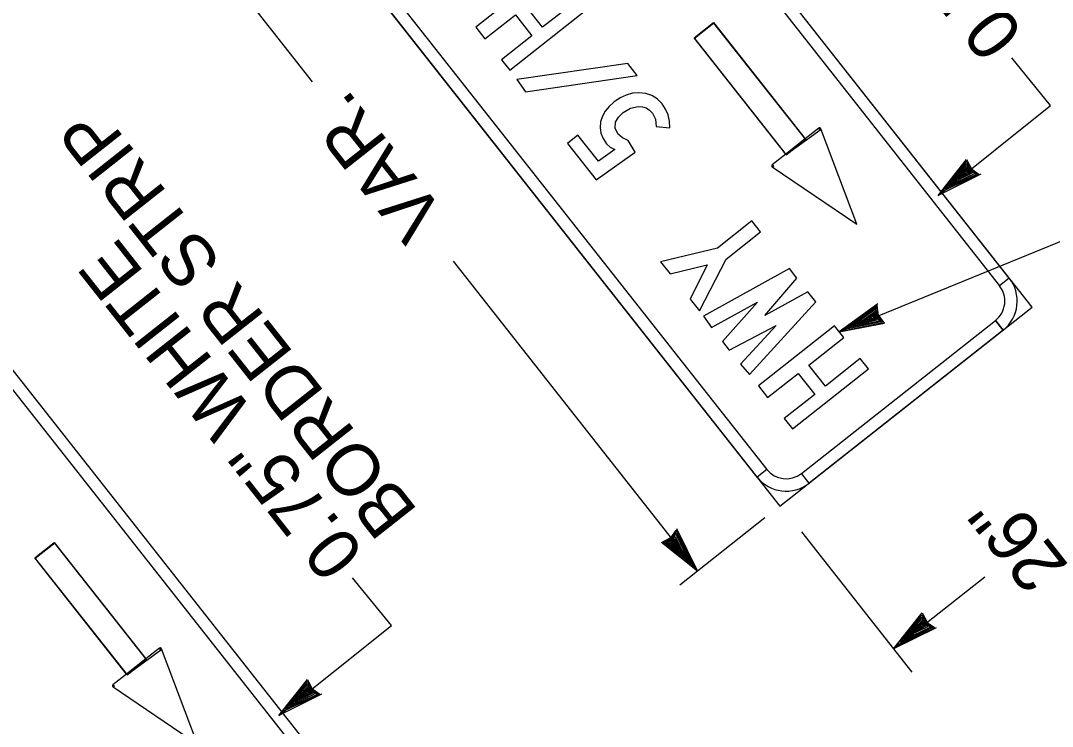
# Model space of a CAD drawing. Extents: x 671946 to 673995, y 1673066 to 1674936.
# Drawn here: x 672680.8 to 672764.3, y 1673606 to 1673663.1 of the extents above; entities that cross this region are included whole.
import ezdxf

# ---------------------------------------------------------------- set-up
doc = ezdxf.new("R2010")
doc.units = 0
doc.layers.add('C-ANNO-SYMB', color=7, linetype='Continuous')
doc.layers.add('Level 1', color=7, linetype='Continuous')

msp = doc.modelspace()

# ---------------------------------------------------------------- linework, layer by layer
at = {"layer": 'C-ANNO-SYMB'}
for p, q in [((672762.708, 1673639.935), (672710.703, 1673705.901)), ((672760.851, 1673642.291), (672712.561, 1673703.545)), ((672711.775, 1673702.926), (672760.065, 1673641.672)), ((672690.285, 1673689.804), (672742.29, 1673623.838)), ((672740.433, 1673626.194), (672692.143, 1673687.449)), ((672692.928, 1673688.068), (672741.218, 1673626.813)), ((672709.345, 1673597.867), (672657.341, 1673663.833)), ((672735.333, 1673661.737), (672736.904, 1673662.975)), ((672736.947, 1673662.921), (672735.376, 1673661.683)), ((672736.904, 1673662.975), (672736.904, 1673662.975)), ((672736.904, 1673662.975), (672736.904, 1673662.975)), ((672736.904, 1673662.975), (672744.333, 1673653.552)), ((672744.376, 1673653.497), (672736.947, 1673662.921)), ((672707.488, 1673600.222), (672659.198, 1673661.477)), ((672742.762, 1673652.314), (672735.333, 1673661.737)), ((672735.376, 1673661.683), (672735.376, 1673661.683)), ((672735.376, 1673661.683), (672735.376, 1673661.683)), ((672735.376, 1673661.683), (672742.805, 1673652.259)), ((672658.413, 1673660.858), (672706.703, 1673599.603)), ((672745.63, 1673654.322), (672742.805, 1673652.259)), ((672745.432, 1673654.418), (672744.333, 1673653.552)), ((672745.494, 1673654.34), (672745.432, 1673654.418)), ((672745.432, 1673654.418), (672745.494, 1673654.34)), ((672745.475, 1673654.364), (672745.537, 1673654.285)), ((672745.537, 1673654.285), (672745.475, 1673654.364)), ((672745.587, 1673654.376), (672745.494, 1673654.34)), ((672745.494, 1673654.34), (672745.587, 1673654.376)), ((672745.537, 1673654.285), (672745.63, 1673654.322)), ((672745.537, 1673654.285), (672745.63, 1673654.322)), ((672748.5, 1673646.65), (672745.587, 1673654.376)), ((672742.762, 1673652.314), (672744.333, 1673653.552)), ((672742.762, 1673652.314), (672744.333, 1673653.552)), ((672744.333, 1673653.552), (672742.762, 1673652.314)), ((672744.376, 1673653.497), (672742.805, 1673652.259)), ((672742.805, 1673652.259), (672744.376, 1673653.497)), ((672742.762, 1673652.314), (672741.663, 1673651.447)), ((672741.663, 1673651.447), (672741.725, 1673651.368)), ((672741.725, 1673651.368), (672741.663, 1673651.447)), ((672741.725, 1673651.368), (672741.668, 1673651.286)), ((672741.668, 1673651.286), (672741.725, 1673651.368)), ((672741.668, 1673651.286), (672748.5, 1673646.65)), ((672741.768, 1673651.314), (672741.706, 1673651.392)), ((672741.706, 1673651.392), (672741.768, 1673651.314)), ((672741.711, 1673651.232), (672741.768, 1673651.314)), ((672741.768, 1673651.314), (672741.711, 1673651.232)), ((672748.5, 1673646.65), (672748.5, 1673646.65)), ((672748.5, 1673646.65), (672748.5, 1673646.65)), ((672748.543, 1673646.596), (672748.543, 1673646.596)), ((672748.543, 1673646.596), (672748.543, 1673646.596)), ((672760.851, 1673642.291), (672760.065, 1673641.672)), ((672760.851, 1673642.291), (672760.065, 1673641.672)), ((672760.065, 1673641.672), (672760.065, 1673641.672)), ((672760.065, 1673641.672), (672760.065, 1673641.672)), ((672742.29, 1673623.838), (672762.708, 1673639.935)), ((672762.708, 1673639.935), (672762.708, 1673639.935)), ((672762.708, 1673639.935), (672762.708, 1673639.935)), ((672744.027, 1673626.481), (672759.733, 1673638.863)), ((672759.733, 1673638.863), (672760.352, 1673638.078)), ((672760.352, 1673638.078), (672759.733, 1673638.863)), ((672760.352, 1673638.078), (672744.646, 1673625.696)), ((672741.218, 1673626.813), (672740.433, 1673626.194)), ((672741.218, 1673626.813), (672740.433, 1673626.194)), ((672744.646, 1673625.696), (672744.027, 1673626.481)), ((672744.027, 1673626.481), (672744.027, 1673626.481)), ((672744.027, 1673626.481), (672744.027, 1673626.481)), ((672744.646, 1673625.696), (672744.027, 1673626.481)), ((672681.971, 1673619.669), (672683.541, 1673620.907)), ((672683.584, 1673620.853), (672682.014, 1673619.614)), ((672683.541, 1673620.907), (672683.541, 1673620.907)), ((672683.541, 1673620.907), (672683.541, 1673620.907)), ((672683.541, 1673620.907), (672690.97, 1673611.483)), ((672691.013, 1673611.429), (672683.584, 1673620.853)), ((672689.4, 1673610.245), (672681.971, 1673619.669)), ((672682.014, 1673619.614), (672682.014, 1673619.614)), ((672682.014, 1673619.614), (672682.014, 1673619.614)), ((672682.014, 1673619.614), (672689.443, 1673610.191)), ((672692.268, 1673612.253), (672689.443, 1673610.191)), ((672692.07, 1673612.35), (672690.97, 1673611.483)), ((672692.132, 1673612.271), (672692.07, 1673612.35)), ((672692.07, 1673612.35), (672692.132, 1673612.271)), ((672692.113, 1673612.296), (672692.175, 1673612.217)), ((672692.175, 1673612.217), (672692.113, 1673612.296)), ((672692.225, 1673612.308), (672692.132, 1673612.271)), ((672692.132, 1673612.271), (672692.225, 1673612.308)), ((672692.175, 1673612.217), (672692.268, 1673612.253)), ((672692.175, 1673612.217), (672692.268, 1673612.253)), ((672695.138, 1673604.582), (672692.225, 1673612.308)), ((672689.4, 1673610.245), (672690.97, 1673611.483)), ((672689.4, 1673610.245), (672690.97, 1673611.483)), ((672690.97, 1673611.483), (672689.4, 1673610.245)), ((672691.013, 1673611.429), (672689.443, 1673610.191)), ((672689.443, 1673610.191), (672691.013, 1673611.429)), ((672689.4, 1673610.245), (672688.3, 1673609.378)), ((672688.3, 1673609.378), (672688.362, 1673609.3)), ((672688.362, 1673609.3), (672688.3, 1673609.378)), ((672688.362, 1673609.3), (672688.305, 1673609.218)), ((672688.305, 1673609.218), (672688.362, 1673609.3)), ((672688.305, 1673609.218), (672695.138, 1673604.582)), ((672688.405, 1673609.245), (672688.343, 1673609.324)), ((672688.343, 1673609.324), (672688.405, 1673609.245)), ((672688.348, 1673609.163), (672688.405, 1673609.245)), ((672688.405, 1673609.245), (672688.348, 1673609.163))]:
    msp.add_line(p, q, dxfattribs=at)
for points in [[(672726.575, 1673663.963), (672725.908, 1673664.808), (672723.081, 1673662.579), (672721.747, 1673664.271), (672724.575, 1673666.5), (672723.832, 1673667.442), (672717.671, 1673662.585), (672718.413, 1673661.643), (672720.884, 1673663.591), (672722.218, 1673661.899), (672719.747, 1673659.951), (672720.413, 1673659.106)], [(672730.735, 1673658.686), (672729.98, 1673659.643), (672720.997, 1673658.365), (672721.701, 1673657.368)], [(672733.379, 1673654.455), (672733.346, 1673654.994), (672733.228, 1673655.494), (672733.028, 1673655.956), (672732.746, 1673656.383), (672732.36, 1673656.782), (672731.921, 1673657.067), (672731.427, 1673657.234), (672730.875, 1673657.286), (672730.351, 1673657.237), (672729.839, 1673657.093), (672729.342, 1673656.858), (672728.855, 1673656.528), (672728.457, 1673656.169), (672728.142, 1673655.782), (672727.916, 1673655.375), (672727.775, 1673654.943), (672727.733, 1673654.476), (672727.795, 1673654.022), (672727.968, 1673653.576), (672728.246, 1673653.147), (672728.533, 1673652.884), (672728.932, 1673652.681), (672727.595, 1673651.736), (672725.938, 1673653.838), (672725.092, 1673653.171), (672727.405, 1673650.237), (672730.567, 1673652.488), (672730.005, 1673653.427), (672729.533, 1673653.635), (672729.163, 1673653.971), (672728.949, 1673654.421), (672728.985, 1673654.899), (672729.209, 1673655.308), (672729.587, 1673655.686), (672730.192, 1673656.043), (672730.813, 1673656.177), (672731.152, 1673656.154), (672731.455, 1673656.053), (672731.732, 1673655.877), (672731.974, 1673655.624), (672732.22, 1673655.137), (672732.272, 1673654.539)], [(672733.39, 1673642.645), (672736.39, 1673643.348), (672735.023, 1673640.574), (672735.767, 1673639.63), (672737.927, 1673643.822), (672740.718, 1673646.022), (672740.018, 1673646.911), (672737.226, 1673644.71), (672732.632, 1673643.608)], [(672745.182, 1673640.361), (672744.533, 1673641.183), (672741.063, 1673639.269), (672743.658, 1673642.294), (672743.058, 1673643.055), (672736.106, 1673639.2), (672736.74, 1673638.292), (672740.483, 1673640.354), (672737.642, 1673637.148), (672738.19, 1673636.453), (672741.986, 1673638.448), (672739.087, 1673635.315), (672739.828, 1673634.479)], [(672749.457, 1673634.938), (672748.79, 1673635.783), (672745.963, 1673633.554), (672744.629, 1673635.246), (672747.457, 1673637.475), (672746.714, 1673638.417), (672740.553, 1673633.56), (672741.295, 1673632.618), (672743.766, 1673634.566), (672745.1, 1673632.874), (672742.629, 1673630.926), (672743.295, 1673630.081)]]:
    msp.add_lwpolyline(points, close=True, dxfattribs=at)
for centre, radius, start, end in [((672745.494, 1673654.34), 0.1, 21.14769, 128.25069), ((672741.725, 1673651.368), 0.1, 128.25069, 235.35312), ((672758.495, 1673640.434), 3, 308.25039, 38.2506), ((672758.495, 1673640.434), 2, 308.25039, 38.2506), ((672742.789, 1673628.052), 2, 218.25075, 308.25039), ((672742.789, 1673628.052), 3, 218.25075, 308.25039), ((672692.132, 1673612.271), 0.1, 21.14769, 128.25069), ((672688.362, 1673609.3), 0.1, 128.25069, 235.35312)]:
    msp.add_arc(centre, radius, start, end, dxfattribs=at)
at = {"layer": 'Level 1'}
for p, q in [((672704.456, 1673658.174), (672683.642, 1673684.577)), ((672755.083, 1673648.981), (672757.402, 1673651.891)), ((672755.3, 1673649.217), (672757.384, 1673651.742)), ((672755.652, 1673649.493), (672757.382, 1673651.574)), ((672757.382, 1673651.574), (672757.52, 1673651.314)), ((672757.384, 1673651.742), (672757.725, 1673651.177)), ((672757.402, 1673651.891), (672757.795, 1673651.132)), ((672758.543, 1673650.687), (672755.083, 1673648.981)), ((672758.185, 1673650.672), (672755.342, 1673649.249)), ((672758.351, 1673650.634), (672755.503, 1673649.341)), ((672755.87, 1673649.593), (672757.425, 1673651.309)), ((672758.064, 1673650.744), (672755.87, 1673649.593)), ((672755.942, 1673649.716), (672757.383, 1673651.443)), ((672758.064, 1673650.744), (672755.942, 1673649.716)), ((672756.376, 1673650.056), (672757.369, 1673651.165)), ((672757.885, 1673650.803), (672756.376, 1673650.056)), ((672756.763, 1673650.325), (672757.334, 1673651.037)), ((672757.723, 1673650.842), (672756.763, 1673650.325)), ((672757.428, 1673651.177), (672756.922, 1673650.419)), ((672757.098, 1673650.621), (672757.364, 1673650.96)), ((672757.615, 1673650.892), (672757.098, 1673650.621)), ((672757.334, 1673651.037), (672757.615, 1673650.892)), ((672757.364, 1673650.96), (672757.446, 1673650.895)), ((672757.369, 1673651.165), (672757.723, 1673650.842)), ((672757.383, 1673651.443), (672758.064, 1673650.744)), ((672757.425, 1673651.309), (672757.885, 1673650.803)), ((672757.804, 1673650.906), (672757.428, 1673651.177)), ((672757.446, 1673650.895), (672757.804, 1673650.906)), ((672757.52, 1673651.314), (672758.064, 1673650.744)), ((672757.725, 1673651.177), (672758.396, 1673650.705)), ((672757.795, 1673651.132), (672758.037, 1673650.822)), ((672758.037, 1673650.822), (672758.351, 1673650.634)), ((672758.396, 1673650.705), (672758.177, 1673650.768)), ((672758.177, 1673650.768), (672758.185, 1673650.672)), ((672756.922, 1673650.419), (672756.669, 1673650.318)), ((672735.617, 1673618.578), (672715.856, 1673643.645)), ((672750.205, 1673640.216), (672747.085, 1673637.946)), ((672750.026, 1673639.905), (672747.443, 1673638.051)), ((672750.069, 1673640.07), (672747.599, 1673638.151)), ((672750.034, 1673639.765), (672747.993, 1673638.359)), ((672750.034, 1673639.765), (672748.136, 1673638.364)), ((672750.107, 1673639.854), (672750.026, 1673639.905)), ((672750.284, 1673639.018), (672750.034, 1673639.765)), ((672750.335, 1673638.837), (672750.034, 1673639.765)), ((672750.089, 1673639.704), (672750.069, 1673640.07)), ((672750.153, 1673640.077), (672750.107, 1673639.854)), ((672750.259, 1673639.263), (672750.153, 1673640.077)), ((672747.993, 1673638.359), (672750.235, 1673638.936)), ((672750.002, 1673639.579), (672748.638, 1673638.59)), ((672748.638, 1673638.59), (672750.082, 1673638.954)), ((672749.961, 1673639.417), (672749.057, 1673638.808)), ((672749.057, 1673638.808), (672749.953, 1673638.982)), ((672750.12, 1673639), (672749.214, 1673638.905)), ((672749.955, 1673639.299), (672749.475, 1673638.967)), ((672749.475, 1673638.967), (672749.899, 1673639.044)), ((672749.88, 1673639.147), (672750.056, 1673639.459)), ((672749.899, 1673639.044), (672749.88, 1673639.147)), ((672749.953, 1673638.982), (672749.955, 1673639.299)), ((672750.082, 1673638.954), (672749.961, 1673639.417)), ((672750.235, 1673638.936), (672750.002, 1673639.579)), ((672750.056, 1673639.459), (672750.12, 1673639)), ((672750.251, 1673639.346), (672750.089, 1673639.704)), ((672750.741, 1673638.645), (672750.251, 1673639.346)), ((672750.601, 1673638.698), (672750.259, 1673639.263)), ((672750.45, 1673638.774), (672750.284, 1673639.018)), ((672747.085, 1673637.946), (672750.741, 1673638.645)), ((672747.396, 1673638.029), (672750.601, 1673638.698)), ((672747.599, 1673638.151), (672747.396, 1673638.029)), ((672747.443, 1673638.051), (672747.566, 1673638.221)), ((672747.566, 1673638.221), (672748.314, 1673638.731)), ((672747.803, 1673638.211), (672750.45, 1673638.774)), ((672748.314, 1673638.731), (672747.803, 1673638.211)), ((672748.136, 1673638.364), (672750.335, 1673638.837)), ((672748.531, 1673638.57), (672748.918, 1673638.859)), ((672749.007, 1673638.728), (672748.531, 1673638.57)), ((672749.214, 1673638.905), (672749.007, 1673638.728)), ((672741.077, 1673622.883), (672734.173, 1673617.44)), ((672733.157, 1673620.88), (672733.856, 1673621.561)), ((672733.286, 1673621.016), (672733.856, 1673621.561)), ((672733.291, 1673620.921), (672733.797, 1673621.382)), ((672733.423, 1673621.222), (672733.896, 1673621.893)), ((672733.468, 1673621.292), (672733.778, 1673621.533)), ((672733.778, 1673621.533), (672733.966, 1673621.848)), ((672733.797, 1673621.382), (672734.543, 1673619.872)), ((672733.896, 1673621.893), (672733.832, 1673621.674)), ((672733.832, 1673621.674), (672733.928, 1673621.682)), ((672733.856, 1673621.561), (672734.883, 1673619.438)), ((672733.856, 1673621.561), (672735.006, 1673619.366)), ((672733.914, 1673622.04), (672735.617, 1673618.578)), ((672733.928, 1673621.682), (672735.35, 1673618.838)), ((672733.966, 1673621.848), (672735.258, 1673618.999)), ((672744.021, 1673621.757), (672752.976, 1673610.397)), ((672732.709, 1673620.9), (672733.468, 1673621.292)), ((672735.617, 1673618.578), (672732.709, 1673620.9)), ((672732.857, 1673620.881), (672733.423, 1673621.222)), ((672735.382, 1673618.796), (672732.857, 1673620.881)), ((672733.026, 1673620.878), (672733.286, 1673621.016)), ((672735.106, 1673619.147), (672733.026, 1673620.878)), ((672734.883, 1673619.438), (672733.157, 1673620.88)), ((672735.006, 1673619.366), (672733.291, 1673620.921)), ((672733.694, 1673621.3), (672733.423, 1673620.924)), ((672733.423, 1673620.924), (672734.181, 1673620.418)), ((672733.435, 1673620.866), (672733.757, 1673621.219)), ((672734.543, 1673619.872), (672733.435, 1673620.866)), ((672733.562, 1673620.831), (672733.708, 1673621.112)), ((672734.274, 1673620.259), (672733.562, 1673620.831)), ((672733.639, 1673620.861), (672733.704, 1673620.943)), ((672733.979, 1673620.595), (672733.639, 1673620.861)), ((672733.704, 1673620.943), (672733.694, 1673621.3)), ((672733.708, 1673621.112), (672733.979, 1673620.595)), ((672733.757, 1673621.219), (672734.274, 1673620.259)), ((672734.181, 1673620.418), (672734.281, 1673620.165)), ((672734.281, 1673620.165), (672734.629, 1673619.804)), ((672734.629, 1673619.804), (672734.421, 1673620.239)), ((672735.32, 1673619.045), (672734.896, 1673619.845)), ((672734.896, 1673619.845), (672735.106, 1673619.147)), ((672735.258, 1673618.999), (672735.382, 1673618.796)), ((672735.35, 1673618.838), (672735.32, 1673619.045)), ((672751.482, 1673612.292), (672758.87, 1673618.117)), ((672751.482, 1673612.292), (672753.803, 1673615.201)), ((672751.7, 1673612.528), (672753.785, 1673615.052)), ((672752.051, 1673612.804), (672753.782, 1673614.884)), ((672752.341, 1673613.027), (672753.784, 1673614.753)), ((672753.782, 1673614.884), (672753.92, 1673614.624)), ((672753.784, 1673614.753), (672754.464, 1673614.054)), ((672753.785, 1673615.052), (672754.126, 1673614.487)), ((672753.803, 1673615.201), (672754.195, 1673614.441)), ((672754.943, 1673613.996), (672751.482, 1673612.292)), ((672754.586, 1673613.982), (672751.742, 1673612.56)), ((672754.751, 1673613.944), (672751.903, 1673612.652)), ((672752.27, 1673612.904), (672753.825, 1673614.619)), ((672754.464, 1673614.054), (672752.27, 1673612.904)), ((672754.464, 1673614.054), (672752.341, 1673613.027)), ((672752.775, 1673613.367), (672753.77, 1673614.475)), ((672754.285, 1673614.113), (672752.775, 1673613.367)), ((672753.163, 1673613.635), (672753.734, 1673614.347)), ((672754.123, 1673614.152), (672753.163, 1673613.635)), ((672753.828, 1673614.487), (672753.322, 1673613.729)), ((672753.498, 1673613.931), (672753.764, 1673614.271)), ((672754.016, 1673614.202), (672753.498, 1673613.931)), ((672753.734, 1673614.347), (672754.016, 1673614.202)), ((672753.764, 1673614.271), (672753.846, 1673614.205)), ((672753.77, 1673614.475), (672754.123, 1673614.152)), ((672753.825, 1673614.619), (672754.285, 1673614.113)), ((672754.204, 1673614.216), (672753.828, 1673614.487)), ((672753.846, 1673614.205), (672754.204, 1673614.216)), ((672753.92, 1673614.624), (672754.464, 1673614.054)), ((672754.126, 1673614.487), (672754.796, 1673614.014)), ((672754.195, 1673614.441), (672754.437, 1673614.132)), ((672754.437, 1673614.132), (672754.751, 1673613.944)), ((672754.796, 1673614.014), (672754.577, 1673614.077)), ((672754.577, 1673614.077), (672754.586, 1673613.982)), ((672753.069, 1673613.629), (672752.707, 1673613.281)), ((672752.707, 1673613.281), (672753.143, 1673613.489)), ((672753.322, 1673613.729), (672753.069, 1673613.629)), ((672751.903, 1673612.652), (672751.7, 1673612.528)), ((672751.742, 1673612.56), (672751.949, 1673612.589)), ((672751.949, 1673612.589), (672752.748, 1673613.014)), ((672752.748, 1673613.014), (672752.051, 1673612.804)), ((672701.72, 1673606.912), (672704.04, 1673609.823)), ((672704.04, 1673609.823), (672704.432, 1673609.063)), ((672701.938, 1673607.148), (672704.022, 1673609.674)), ((672702.289, 1673607.424), (672704.019, 1673609.506)), ((672702.508, 1673607.524), (672704.062, 1673609.24)), ((672702.579, 1673607.648), (672704.021, 1673609.374)), ((672703.013, 1673607.987), (672704.007, 1673609.096)), ((672703.4, 1673608.257), (672703.971, 1673608.969)), ((672704.065, 1673609.109), (672703.56, 1673608.35)), ((672703.736, 1673608.552), (672704.001, 1673608.892)), ((672703.971, 1673608.969), (672704.253, 1673608.823)), ((672704.001, 1673608.892), (672704.084, 1673608.827)), ((672704.007, 1673609.096), (672704.36, 1673608.774)), ((672704.019, 1673609.506), (672704.157, 1673609.246)), ((672704.021, 1673609.374), (672704.702, 1673608.676)), ((672704.022, 1673609.674), (672704.363, 1673609.109)), ((672704.062, 1673609.24), (672704.523, 1673608.735)), ((672704.441, 1673608.838), (672704.065, 1673609.109)), ((672704.157, 1673609.246), (672704.702, 1673608.676)), ((672704.363, 1673609.109), (672705.034, 1673608.636)), ((672704.432, 1673609.063), (672704.674, 1673608.753)), ((672705.181, 1673608.618), (672701.72, 1673606.912)), ((672704.823, 1673608.604), (672701.98, 1673607.18)), ((672704.989, 1673608.566), (672702.141, 1673607.272)), ((672704.702, 1673608.676), (672702.508, 1673607.524)), ((672704.702, 1673608.676), (672702.579, 1673607.648)), ((672704.523, 1673608.735), (672703.013, 1673607.987)), ((672703.56, 1673608.35), (672703.306, 1673608.25)), ((672704.36, 1673608.774), (672703.4, 1673608.257)), ((672704.253, 1673608.823), (672703.736, 1673608.552)), ((672704.084, 1673608.827), (672704.441, 1673608.838)), ((672704.674, 1673608.753), (672704.989, 1673608.566)), ((672705.034, 1673608.636), (672704.815, 1673608.699)), ((672704.815, 1673608.699), (672704.823, 1673608.604))]:
    msp.add_line(p, q, dxfattribs=at)
for points in [[(672755.083, 1673648.981), (672764.195, 1673656.242), (672761.058, 1673660.098)], [(672747.085, 1673637.946), (672769.798, 1673647.204), (672771.021, 1673645.654)], [(672701.72, 1673606.912), (672710.833, 1673614.173), (672707.695, 1673618.029)]]:
    msp.add_lwpolyline(points, dxfattribs=at)

# ---------------------------------------------------------------- texts
for s, p in [('0.75" WHITE ', (672762.128, 1673662.109)), ('VAR.', (672715.303, 1673647.396)), ('BORDER STRIP', (672713.06, 1673623.426)), ('0.75" WHITE ', (672708.766, 1673620.041)), ('26"', (672765.736, 1673619.017))]:
    msp.add_text(s, height=4.2, rotation=128.25054, dxfattribs=at).set_placement(p)

doc.saveas('drawing.dxf')
